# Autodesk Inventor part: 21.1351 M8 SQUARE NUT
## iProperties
Created: 2006-12
Part Number: 21.1351 M8 SQUARE NUT
Document SubType Name: Modeling
Designer: Andy Moles
Material: Steel, Mild
Mass: 3.99144 g
Surface Area: 5.54975 cm^2
Volume: 0.507817 cm^3
Density: 7.86 g/cm^3
Author: Andy Moles
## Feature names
1. Extrusion1
2. Revolution1
